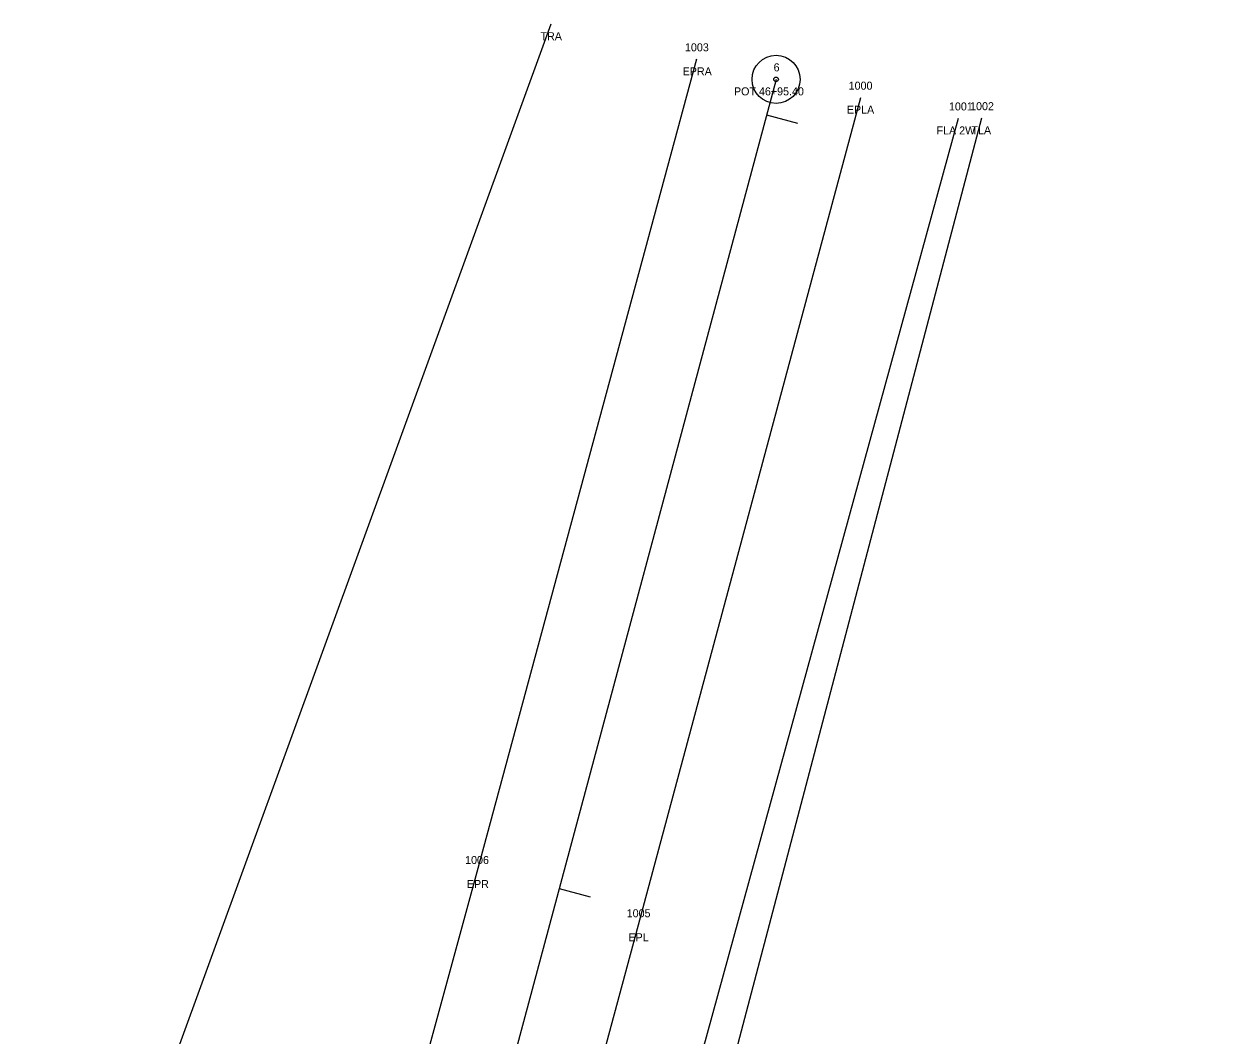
# Model space of a CAD drawing. Extents: x 2432632 to 2433497, y 684847 to 688233.
# Drawn here: x 2433046.6 to 2433197.4, y 687968.3 to 688094.6 of the extents above; entities that cross this region are included whole.
import ezdxf

# ---------------------------------------------------------------- set-up
doc = ezdxf.new("R2010")
doc.units = 0
for name, color, linetype in [('RD_EX_Fence_Other', 7, 'Continuous'), ('RD_EX_Fence_Other_txCode', 7, 'Continuous'), ('RD_EX_Road', 7, 'Continuous'), ('RD_EX_Road_txCode', 7, 'Continuous'), ('RD_EX_VEG', 7, 'Continuous'), ('RD_EX_VEG_txCode', 7, 'Continuous'), ('RD_HC_Cl', 7, 'Continuous'), ('RD_HC_Data', 7, 'Continuous'), ('RD_HC_Data_Tic', 7, 'Continuous'), ('RD_HC_txCode', 7, 'Continuous'), ('RD_SMD_Locator', 7, 'Continuous')]:
    doc.layers.add(name, color=color, linetype=linetype)

msp = doc.modelspace()

# ---------------------------------------------------------------- linework, layer by layer
at = {"layer": 'RD_EX_Fence_Other'}
msp.add_lwpolyline([(2433163.32, 688082.84), (2433107.2, 687878.29), (2433065.65, 687704.2), (2433063.62, 687678.63), (2433060.64, 687652.01)], dxfattribs=at)
at = {"layer": 'RD_EX_Road'}
for points in [[(2433130.63, 688090.22), (2433103.18, 687988.73), (2433075.68, 687887.89), (2433049.83, 687790.75), (2433022.33, 687689.17), (2432994.76, 687586.82), (2432966.23, 687480.17), (2432943.15, 687390.42), (2432931.4, 687334.3), (2432921.83, 687273.88), (2432915.64, 687215.4), (2432913.86, 687159.12), (2432915.08, 687107.55), (2432919.97, 687053.4), (2432928.7, 686998.89), (2432946.77, 686924.59), (2432964.57, 686864), (2432997.3, 686766.34), (2433031.44, 686666.38), (2433066.06, 686565.78), (2433098.73, 686469.74)], [(2433151.11, 688085.43), (2433123.35, 687982.08), (2433096.36, 687882.07), (2433070.62, 687785.25), (2433042.64, 687684.31), (2433015.24, 687582.49), (2432986.34, 687474.01), (2432964, 687384.38)]]:
    msp.add_lwpolyline(points, dxfattribs=at)
at = {"layer": 'RD_EX_VEG'}
for points in [[(2433112.43, 688094.61), (2433041.17, 687898.89), (2432988.9, 687699.78), (2432947.96, 687578.08), (2432935.9, 687556.87), (2432944.3, 687538.7), (2432913.88, 687397.98), (2432902.4, 687330.02), (2432885.78, 687157.56), (2432894.43, 687032.93), (2432918.07, 686924.4), (2432974.73, 686759.54), (2433073.82, 686456.42), (2433099.9, 686365.23), (2433115.47, 686257.21), (2433114.64, 686158.77), (2433095.68, 686092.78)], [(2433166.25, 688082.87), (2433111.93, 687876.69), (2433067.75, 687703.46), (2433065.05, 687678.03), (2433052.74, 687645.62), (2433005.45, 687469.88), (2432979.96, 687326.61), (2432966.8, 687267.34), (2432959.05, 687210.65), (2432959.25, 687071.62), (2432974.82, 687014.37), (2432998.13, 686938.9), (2433012.99, 686878.7), (2433054.45, 686782.35), (2433123.54, 686586.06), (2433129.82, 686546.35), (2433158.34, 686434.26), (2433192.79, 686274.67), (2433189.42, 686162.6), (2433197.4, 686074.41)]]:
    msp.add_lwpolyline(points, dxfattribs=at)
at = {"layer": 'RD_HC_Cl'}
msp.add_line((2433140.58, 688087.72), (2432956.34, 687400.83), dxfattribs=at)
at = {"layer": 'RD_HC_Data'}
for radius in [3, 0.282]:
    msp.add_circle((2433140.58, 688087.72), radius, dxfattribs=at)
at = {"layer": 'RD_HC_Data_Tic'}
for p, q in [((2433139.38, 688083.28), (2433143.25, 688082.24)), ((2433113.48, 687986.69), (2433117.34, 687985.65))]:
    msp.add_line(p, q, dxfattribs=at)
at = {"layer": 'RD_SMD_Locator'}
for centre in [(2433112.43, 688094.61), (2433130.63, 688090.22), (2433140.58, 688087.72), (2433151.11, 688085.43), (2433163.32, 688082.84), (2433166.25, 688082.87), (2433103.18, 687988.73), (2433123.35, 687982.08)]:
    msp.add_circle(centre, 0.001, dxfattribs=at)

# ---------------------------------------------------------------- texts
at = {"layer": 'RD_EX_Fence_Other_txCode'}
for s, p in [('1001', (2433162.18, 688083.84)), ('FLA 2W', (2433160.63, 688080.84))]:
    msp.add_text(s, height=1, dxfattribs=at).set_placement(p)
at = {"layer": 'RD_EX_Road_txCode'}
for s, p in [('1003', (2433129.2, 688091.22)), ('EPRA', (2433128.91, 688088.22)), ('1000', (2433149.65, 688086.43)), ('EPLA', (2433149.42, 688083.43)), ('1006', (2433101.73, 687989.73)), ('EPR', (2433101.95, 687986.73)), ('1005', (2433121.92, 687983.08)), ('EPL', (2433122.14, 687980.08))]:
    msp.add_text(s, height=1, dxfattribs=at).set_placement(p)
at = {"layer": 'RD_EX_VEG_txCode'}
for s, p in [('TRA', (2433111.15, 688092.61)), ('1002', (2433164.82, 688083.87)), ('TLA', (2433164.99, 688080.87))]:
    msp.add_text(s, height=1, dxfattribs=at).set_placement(p)
at = {"layer": 'RD_HC_txCode'}
for s, p in [('6', (2433140.27, 688088.72)), ('POT 46+95.40', (2433135.32, 688085.72))]:
    msp.add_text(s, height=1, dxfattribs=at).set_placement(p)

doc.saveas('drawing.dxf')
